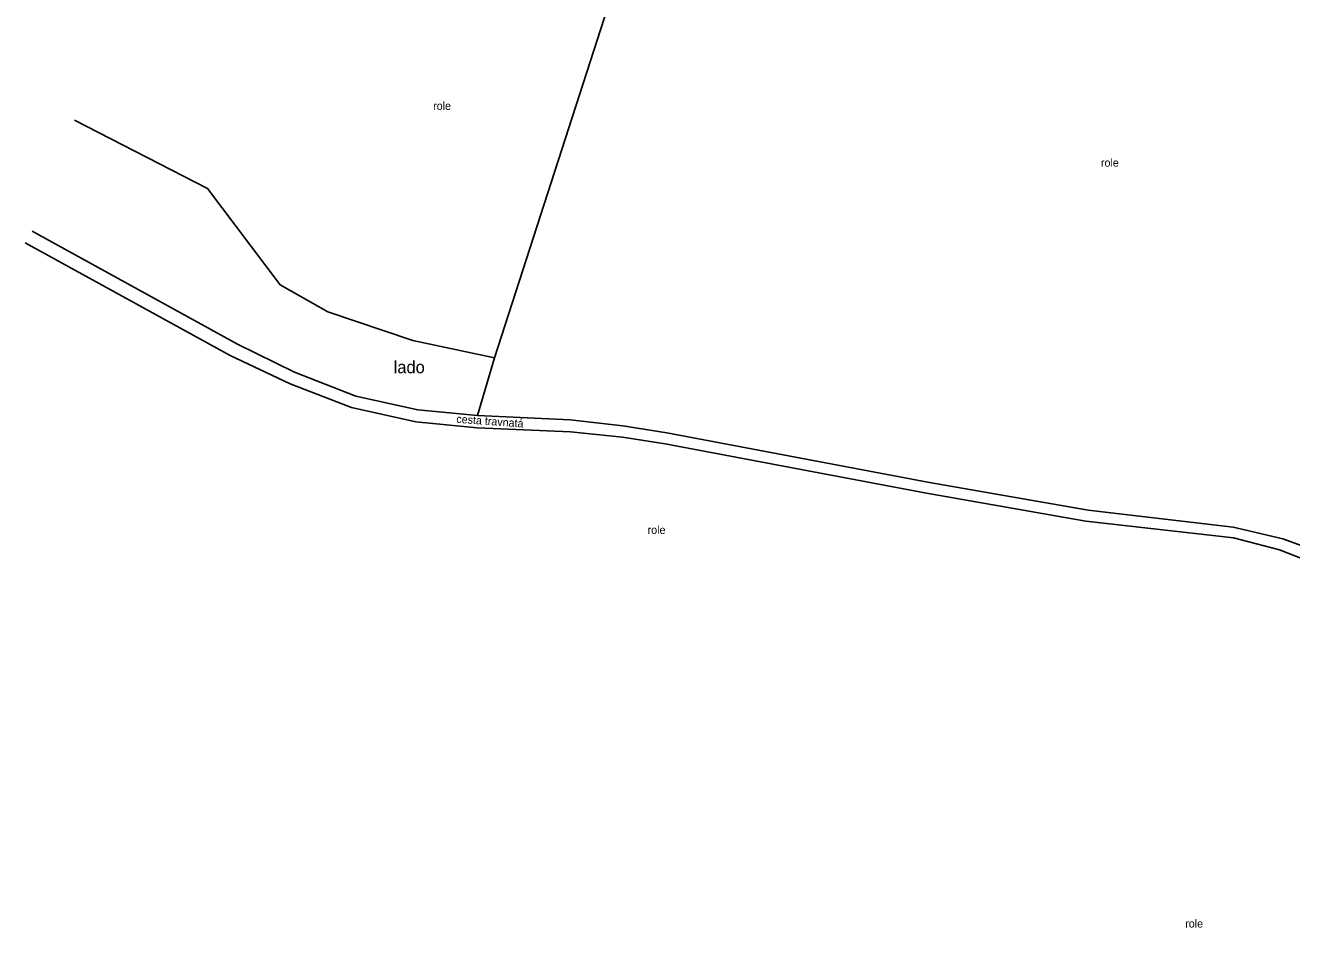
# Model space of a CAD drawing. Extents: x -661586 to -658793, y -1053889 to -1051031.
# Drawn here: x -661585.6 to -661111, y -1053310.2 to -1052972.2 of the extents above; entities that cross this region are included whole.
import ezdxf

# ---------------------------------------------------------------- set-up
doc = ezdxf.new("R2010")
doc.units = 0
doc.layers.add('Vrstva 52', color=7, linetype='Continuous')
doc.layers.add('Vrstva 53', color=7, linetype='Continuous')

msp = doc.modelspace()

# ---------------------------------------------------------------- linework, layer by layer
at = {"layer": 'Vrstva 52'}
for p, q in [((-661567.09, -1053007.75), (-661567.09, -1053007.75)), ((-661583.03, -1053049.31), (-661506.11, -1053091.67)), ((-661585.56, -1053053.71), (-661508.81, -1053095.86)), ((-661506.11, -1053091.67), (-661484.66, -1053102.15)), ((-661508.81, -1053095.86), (-661486.35, -1053106.49)), ((-661484.66, -1053102.15), (-661461.69, -1053111.09)), ((-661486.35, -1053106.49), (-661463.3, -1053115.38)), ((-661461.69, -1053111.09), (-661438.5, -1053116.21)), ((-661463.3, -1053115.38), (-661439.18, -1053120.75)), ((-661438.5, -1053116.21), (-661416.07, -1053118.34)), ((-661439.18, -1053120.75), (-661416.24, -1053122.95)), ((-661416.07, -1053118.34), (-661381.44, -1053119.96)), ((-661381.44, -1053119.96), (-661361.72, -1053122.22)), ((-661416.24, -1053122.95), (-661381.25, -1053124.48)), ((-661381.25, -1053124.48), (-661361.76, -1053126.44)), ((-661361.72, -1053122.22), (-661345.21, -1053124.78)), ((-661345.21, -1053124.78), (-661246.69, -1053143.39)), ((-661361.76, -1053126.44), (-661345.86, -1053128.92)), ((-661345.86, -1053128.92), (-661247.85, -1053147.39)), ((-661246.69, -1053143.39), (-661187.35, -1053153.8)), ((-661247.85, -1053147.39), (-661188.16, -1053157.88)), ((-661187.35, -1053153.8), (-661132.98, -1053160.14)), ((-661188.16, -1053157.88), (-661132.86, -1053164.13)), ((-661132.98, -1053160.14), (-661114.4, -1053164.59)), ((-661132.86, -1053164.13), (-661115.58, -1053168.68)), ((-661114.4, -1053164.59), (-661099.83, -1053169.88)), ((-661115.58, -1053168.68), (-661101.83, -1053174.07))]:
    msp.add_line(p, q, dxfattribs=at)
at = {"layer": 'Vrstva 53'}
for p, q in [((-661409.77, -1053096.75), (-661367.3, -1052965.42)), ((-661567.09, -1053007.75), (-661517.33, -1053033.31)), ((-661517.33, -1053033.31), (-661490.07, -1053069.35)), ((-661490.07, -1053069.35), (-661472.15, -1053079.48)), ((-661472.15, -1053079.48), (-661440.33, -1053090.18)), ((-661440.33, -1053090.18), (-661409.77, -1053096.75)), ((-661416.07, -1053118.34), (-661409.77, -1053096.75))]:
    msp.add_line(p, q, dxfattribs=at)

# ---------------------------------------------------------------- texts
at = {"layer": 'Vrstva 52'}
for p in [(-661432.751, -1053003.835), (-661182.509, -1053025.126), (-661352.386, -1053162.706), (-661150.943, -1053310.181)]:
    msp.add_text('role', height=3, dxfattribs=at).set_placement(p)
msp.add_text('cesta travnatá', height=3, rotation=355.92138, dxfattribs=at).set_placement((-661424.131, -1053121.056))
at = {"layer": 'Vrstva 53'}
msp.add_text('lado', height=4.6, dxfattribs=at).set_placement((-661447.519, -1053102.502))

doc.saveas('drawing.dxf')
